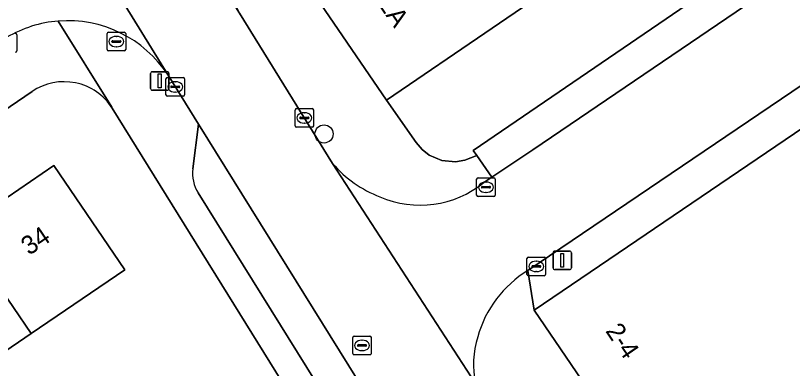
# Model space of a CAD drawing. Extents: x 160030 to 160839, y 385325 to 386450.
# Drawn here: x 160237.55 to 160279.41, y 386008.65 to 386027.68 of the extents above; entities that cross this region are included whole.
import ezdxf

# ---------------------------------------------------------------- set-up
doc = ezdxf.new("R2010")
doc.units = 0
for name, color, linetype in [('IMGEO_Boom', 7, 'Continuous'), ('IMGEO_Brandkraan', 7, 'Continuous'), ('IMGEO_Erf', 7, 'Continuous'), ('IMGEO_Kolk', 7, 'Continuous'), ('IMGEO_Lichtmast', 7, 'Continuous'), ('IMGEO_Pand', 7, 'Continuous'), ('IMGEO_Pand_nummerreeks', 7, 'Continuous'), ('IMGEO_Parkeervlak_open', 7, 'Continuous'), ('IMGEO_Rijbaan_lokaal_open', 7, 'Continuous'), ('IMGEO_Rioolput', 7, 'Continuous'), ('IMGEO_Voetpad_open', 7, 'Continuous')]:
    doc.layers.add(name, color=color, linetype=linetype)

msp = doc.modelspace()

# ---------------------------------------------------------------- linework, layer by layer
at = {"layer": 'IMGEO_Boom'}
msp.add_circle((160254.174, 386021.293), 0.489, dxfattribs=at)
at = {"layer": 'IMGEO_Brandkraan'}
for p, q in [((160242.484, 386025.846), (160242.484, 386026.698)), ((160242.559, 386026.772), (160243.411, 386026.772)), ((160242.972, 386026.552), (160242.997, 386026.552)), ((160243.485, 386026.698), (160243.485, 386025.846)), ((160242.743, 386026.266), (160242.743, 386026.278)), ((160243.181, 386026.229), (160242.783, 386026.229)), ((160242.786, 386026.315), (160243.184, 386026.315)), ((160243.227, 386026.278), (160243.227, 386026.266)), ((160243.411, 386025.772), (160242.559, 386025.772)), ((160242.995, 386025.992), (160242.97, 386025.992))]:
    msp.add_line(p, q, dxfattribs=at)
for points in [[(160242.484, 386025.846), (160242.484, 386026.698)], [(160242.559, 386026.772), (160243.411, 386026.772)], [(160243.485, 386026.698), (160243.485, 386025.846)], [(160243.411, 386025.772), (160242.559, 386025.772)]]:
    msp.add_lwpolyline(points, dxfattribs=at)
for centre, radius, start, end in [((160242.561, 386026.696), 0.0765, 91.552, 178.448), ((160242.561, 386026.696), 0.0765, 91.552, 178.448), ((160243.409, 386026.696), 0.0765, 1.552, 88.448), ((160243.409, 386026.696), 0.0765, 1.552, 88.448), ((160242.783, 386026.275), 0.0403, 85.8775, 175.7526), ((160242.78, 386026.265), 0.0366, 178.938, 274.7102), ((160243.184, 386026.272), 0.043, 264.8664, 352.4533), ((160243.188, 386026.277), 0.0386, 1.7309, 96.639), ((160242.561, 386025.848), 0.0765, 181.552, 268.448), ((160242.561, 386025.848), 0.0765, 181.552, 268.448), ((160243.409, 386025.848), 0.0765, 271.552, 358.448), ((160243.409, 386025.848), 0.0765, 271.552, 358.448)]:
    msp.add_arc(centre, radius, start, end, dxfattribs=at)
for centre, major_axis, ratio, start_param, end_param in [((160242.971, 386026.272), (-0.387, 0.002), 0.722429, 4.712389, 7.853982), ((160242.996, 386026.272), (-0.39, 0.002), 0.717154, 1.570796, 4.712389)]:
    msp.add_ellipse(centre, major_axis=major_axis, ratio=ratio, start_param=start_param, end_param=end_param, dxfattribs=at)
at = {"layer": 'IMGEO_Erf'}
for points in [[(160238.441, 386023.576), (160203.867, 386000)], [(160238.946, 385999.054), (160242.894, 386001.783), (160244.457, 385999.522), (160246.125, 386000.76), (160244.845, 386002.826), (160248.858, 386005.313), (160250.138, 386003.246), (160253.52, 386005.344), (160242.761, 386022.685)], [(160219.688, 386006.009), (160224.645, 386009.389), (160229.603, 386012.769), (160234.561, 386016.148), (160239.606, 386019.588), (160243.436, 386013.97), (160238.391, 386010.53), (160233.433, 386007.151)]]:
    msp.add_lwpolyline(points, dxfattribs=at)
msp.add_arc((160240.169, 386021.037), 3.071, 32.4491, 124.2432, dxfattribs=at)
at = {"layer": 'IMGEO_Kolk'}
for p, q in [((160237.625, 386026.628), (160237.625, 386025.776)), ((160245.654, 386023.404), (160245.654, 386024.256)), ((160245.729, 386024.33), (160246.581, 386024.33)), ((160246.142, 386024.11), (160246.167, 386024.11)), ((160246.655, 386024.256), (160246.655, 386023.404)), ((160245.913, 386023.824), (160245.913, 386023.836)), ((160246.351, 386023.787), (160245.953, 386023.787)), ((160245.956, 386023.873), (160246.354, 386023.873)), ((160246.397, 386023.836), (160246.397, 386023.824)), ((160246.581, 386023.33), (160245.729, 386023.33)), ((160246.165, 386023.55), (160246.14, 386023.55)), ((160252.612, 386021.73), (160252.612, 386022.582)), ((160252.687, 386022.656), (160253.539, 386022.656)), ((160253.1, 386022.436), (160253.125, 386022.436)), ((160253.613, 386022.582), (160253.613, 386021.73)), ((160252.871, 386022.15), (160252.871, 386022.162)), ((160253.309, 386022.113), (160252.911, 386022.113)), ((160252.914, 386022.199), (160253.312, 386022.199)), ((160253.355, 386022.162), (160253.355, 386022.15)), ((160253.539, 386021.656), (160252.687, 386021.656)), ((160253.123, 386021.876), (160253.098, 386021.876)), ((160262.393, 386017.996), (160262.393, 386018.848)), ((160262.468, 386018.922), (160263.32, 386018.922)), ((160262.881, 386018.702), (160262.906, 386018.702)), ((160263.394, 386018.848), (160263.394, 386017.996)), ((160262.652, 386018.416), (160262.652, 386018.428)), ((160263.09, 386018.379), (160262.692, 386018.379)), ((160262.695, 386018.465), (160263.093, 386018.465)), ((160263.136, 386018.428), (160263.136, 386018.416)), ((160263.32, 386017.922), (160262.468, 386017.922)), ((160262.904, 386018.142), (160262.879, 386018.142)), ((160265.106, 386013.724), (160265.106, 386014.576)), ((160265.181, 386014.65), (160266.033, 386014.65)), ((160265.594, 386014.43), (160265.619, 386014.43)), ((160266.107, 386014.576), (160266.107, 386013.724)), ((160265.365, 386014.144), (160265.365, 386014.156)), ((160265.803, 386014.107), (160265.405, 386014.107)), ((160265.408, 386014.193), (160265.806, 386014.193)), ((160265.849, 386014.156), (160265.849, 386014.144)), ((160266.033, 386013.65), (160265.181, 386013.65)), ((160265.617, 386013.87), (160265.592, 386013.87))]:
    msp.add_line(p, q, dxfattribs=at)
for points in [[(160237.625, 386026.628), (160237.625, 386025.776)], [(160245.654, 386023.404), (160245.654, 386024.256)], [(160245.729, 386024.33), (160246.581, 386024.33)], [(160246.655, 386024.256), (160246.655, 386023.404)], [(160246.581, 386023.33), (160245.729, 386023.33)], [(160252.612, 386021.73), (160252.612, 386022.582)], [(160252.687, 386022.656), (160253.539, 386022.656)], [(160253.613, 386022.582), (160253.613, 386021.73)], [(160253.539, 386021.656), (160252.687, 386021.656)], [(160262.393, 386017.996), (160262.393, 386018.848)], [(160262.468, 386018.922), (160263.32, 386018.922)], [(160263.394, 386018.848), (160263.394, 386017.996)], [(160263.32, 386017.922), (160262.468, 386017.922)], [(160265.106, 386013.724), (160265.106, 386014.576)], [(160265.181, 386014.65), (160266.033, 386014.65)], [(160266.107, 386014.576), (160266.107, 386013.724)], [(160266.033, 386013.65), (160265.181, 386013.65)]]:
    msp.add_lwpolyline(points, dxfattribs=at)
for centre, radius, start, end in [((160237.549, 386026.626), 0.0765, 1.552, 88.448), ((160237.549, 386026.626), 0.0765, 1.552, 88.448), ((160237.549, 386025.778), 0.0765, 271.552, 358.448), ((160237.549, 386025.778), 0.0765, 271.552, 358.448), ((160245.731, 386024.254), 0.0765, 91.552, 178.448), ((160245.731, 386024.254), 0.0765, 91.552, 178.448), ((160246.579, 386024.254), 0.0765, 1.552, 88.448), ((160246.579, 386024.254), 0.0765, 1.552, 88.448), ((160245.953, 386023.833), 0.0403, 85.8775, 175.7526), ((160245.95, 386023.823), 0.0366, 178.938, 274.7102), ((160246.354, 386023.83), 0.043, 264.8664, 352.4533), ((160246.358, 386023.835), 0.0386, 1.7309, 96.639), ((160245.731, 386023.406), 0.0765, 181.552, 268.448), ((160245.731, 386023.406), 0.0765, 181.552, 268.448), ((160246.579, 386023.406), 0.0765, 271.552, 358.448), ((160246.579, 386023.406), 0.0765, 271.552, 358.448), ((160252.689, 386022.58), 0.0765, 91.552, 178.448), ((160252.689, 386022.58), 0.0765, 91.552, 178.448), ((160253.537, 386022.58), 0.0765, 1.552, 88.448), ((160253.537, 386022.58), 0.0765, 1.552, 88.448), ((160252.911, 386022.159), 0.0403, 85.8775, 175.7526), ((160252.908, 386022.149), 0.0366, 178.938, 274.7102), ((160253.312, 386022.156), 0.043, 264.8664, 352.4533), ((160253.316, 386022.161), 0.0386, 1.7309, 96.639), ((160252.689, 386021.732), 0.0765, 181.552, 268.448), ((160252.689, 386021.732), 0.0765, 181.552, 268.448), ((160253.537, 386021.732), 0.0765, 271.552, 358.448), ((160253.537, 386021.732), 0.0765, 271.552, 358.448), ((160262.47, 386018.846), 0.0765, 91.552, 178.448), ((160262.47, 386018.846), 0.0765, 91.552, 178.448), ((160263.318, 386018.846), 0.0765, 1.552, 88.448), ((160263.318, 386018.846), 0.0765, 1.552, 88.448), ((160262.692, 386018.425), 0.0403, 85.8775, 175.7526), ((160262.689, 386018.415), 0.0366, 178.938, 274.7102), ((160263.093, 386018.422), 0.043, 264.8664, 352.4533), ((160263.097, 386018.427), 0.0386, 1.7309, 96.639), ((160262.47, 386017.998), 0.0765, 181.552, 268.448), ((160262.47, 386017.998), 0.0765, 181.552, 268.448), ((160263.318, 386017.998), 0.0765, 271.552, 358.448), ((160263.318, 386017.998), 0.0765, 271.552, 358.448), ((160265.183, 386014.574), 0.0765, 91.552, 178.448), ((160265.183, 386014.574), 0.0765, 91.552, 178.448), ((160266.031, 386014.574), 0.0765, 1.552, 88.448), ((160266.031, 386014.574), 0.0765, 1.552, 88.448), ((160265.405, 386014.153), 0.0403, 85.8775, 175.7526), ((160265.402, 386014.143), 0.0366, 178.938, 274.7102), ((160265.806, 386014.15), 0.043, 264.8664, 352.4533), ((160265.81, 386014.155), 0.0386, 1.7309, 96.639), ((160265.183, 386013.726), 0.0765, 181.552, 268.448), ((160265.183, 386013.726), 0.0765, 181.552, 268.448), ((160266.031, 386013.726), 0.0765, 271.552, 358.448), ((160266.031, 386013.726), 0.0765, 271.552, 358.448)]:
    msp.add_arc(centre, radius, start, end, dxfattribs=at)
for centre, major_axis, ratio, start_param, end_param in [((160246.141, 386023.83), (-0.387, 0.002), 0.722429, 4.712389, 7.853982), ((160246.166, 386023.83), (-0.39, 0.002), 0.717154, 1.570796, 4.712389), ((160253.099, 386022.156), (-0.387, 0.002), 0.722429, 4.712389, 7.853982), ((160253.124, 386022.156), (-0.39, 0.002), 0.717154, 1.570796, 4.712389), ((160262.88, 386018.422), (-0.387, 0.002), 0.722429, 4.712389, 7.853982), ((160262.905, 386018.422), (-0.39, 0.002), 0.717154, 1.570796, 4.712389), ((160265.593, 386014.15), (-0.387, 0.002), 0.722429, 4.712389, 7.853982), ((160265.618, 386014.15), (-0.39, 0.002), 0.717154, 1.570796, 4.712389)]:
    msp.add_ellipse(centre, major_axis=major_axis, ratio=ratio, start_param=start_param, end_param=end_param, dxfattribs=at)
at = {"layer": 'IMGEO_Lichtmast'}
for p, q in [((160244.824, 386023.749), (160244.824, 386024.549)), ((160244.824, 386024.549), (160244.824, 386023.749)), ((160244.924, 386024.649), (160245.714, 386024.649)), ((160245.714, 386024.649), (160244.924, 386024.649)), ((160245.814, 386024.549), (160245.814, 386023.749)), ((160245.814, 386023.749), (160245.814, 386024.549)), ((160245.714, 386023.649), (160244.924, 386023.649)), ((160244.924, 386023.649), (160245.714, 386023.649)), ((160266.512, 386014.08), (160266.512, 386014.88)), ((160266.512, 386014.88), (160266.512, 386014.08)), ((160266.612, 386014.98), (160267.402, 386014.98)), ((160267.402, 386014.98), (160266.612, 386014.98)), ((160267.502, 386014.88), (160267.502, 386014.08)), ((160267.502, 386014.08), (160267.502, 386014.88)), ((160267.402, 386013.98), (160266.612, 386013.98)), ((160266.612, 386013.98), (160267.402, 386013.98))]:
    msp.add_line(p, q, dxfattribs=at)
for points in [[(160245.244, 386024.524), (160245.394, 386024.524), (160245.394, 386023.774), (160245.244, 386023.774), (160245.244, 386024.524)], [(160266.932, 386014.855), (160267.082, 386014.855), (160267.082, 386014.105), (160266.932, 386014.105), (160266.932, 386014.855)]]:
    msp.add_lwpolyline(points, dxfattribs=at)
for centre, start, end in [((160244.924, 386024.549), 90, 180), ((160244.924, 386024.549), 90, 180), ((160245.714, 386024.549), 0, 90), ((160245.714, 386024.549), 360, 90), ((160244.924, 386023.749), 180, 270), ((160244.924, 386023.749), 180, 270), ((160245.714, 386023.749), 270, 0), ((160245.714, 386023.749), 270, 0), ((160266.612, 386014.88), 90, 180), ((160266.612, 386014.88), 90, 180), ((160267.402, 386014.88), 0, 90), ((160267.402, 386014.88), 360, 90), ((160266.612, 386014.08), 180, 270), ((160266.612, 386014.08), 180, 270), ((160267.402, 386014.08), 270, 0), ((160267.402, 386014.08), 270, 0)]:
    msp.add_arc(centre, 0.1, start, end, dxfattribs=at)
at = {"layer": 'IMGEO_Pand'}
msp.add_lwpolyline([(160329.094, 386054.994), (160265.499, 386011.79), (160270.054, 386005.085)], dxfattribs=at)
for points in [[(160286.007, 386042.54), (160285.171, 386043.767), (160281.819, 386048.768), (160281.71, 386048.693), (160279.189, 386046.974), (160265.251, 386037.468), (160262.185, 386035.376), (160253.307, 386029.321), (160257.536, 386023.121)], [(160238.391, 386010.53), (160243.436, 386013.97), (160239.606, 386019.588), (160234.561, 386016.148)], [(160233.433, 386007.151), (160238.391, 386010.53), (160234.561, 386016.148), (160229.603, 386012.769)]]:
    msp.add_lwpolyline(points, close=True, dxfattribs=at)
at = {"layer": 'IMGEO_Parkeervlak_open'}
for points in [[(160247.407, 386021.819), (160247.102, 386019.418)], [(160265.703, 385991.996), (160260.98, 386000), (160258.344, 386004.227), (160247.407, 386021.819)], [(160247.388, 386018.111), (160256.668, 386003.183), (160258.653, 386000), (160260.614, 385996.846), (160261.948, 385994.543)]]:
    msp.add_lwpolyline(points, dxfattribs=at)
msp.add_arc((160249.096, 386019.169), 2.009, 172.893, 211.793, dxfattribs=at)
at = {"layer": 'IMGEO_Rijbaan_lokaal_open'}
for points in [[(160189.926, 386114.094), (160191.24, 386111.976), (160198.933, 386099.578), (160234.281, 386042.907), (160236.171, 386039.885), (160236.489, 386039.496), (160245.768, 386024.457), (160247.407, 386021.819), (160258.344, 386004.227), (160260.98, 386000), (160265.703, 385991.996)], [(160262.33, 386007.837), (160254.635, 386019.699), (160249.611, 386027.802), (160240.779, 386041.933), (160240.647, 386042.176), (160219.316, 386076.396)], [(160325.342, 386061.172), (160323.666, 386060.015), (160315.833, 386054.695), (160308.389, 386049.542), (160302.814, 386045.834), (160265.416, 386020.437), (160263.212, 386018.961), (160262.779, 386018.671)], [(160265.152, 386013.927), (160289.489, 386030.427), (160310.109, 386044.387), (160328.103, 386056.609)], [(160245.768, 386024.457), (160236.489, 386039.496), (160236.171, 386039.885)], [(160254.635, 386019.699), (160262.33, 386007.837)]]:
    msp.add_lwpolyline(points, dxfattribs=at)
msp.add_lwpolyline([(160259.141, 386020.837), (160259.455, 386020.461), (160259.843, 386020.155), (160260.524, 386019.862), (160261.262, 386019.794), (160261.75, 386019.877), (160262.397, 386020.134), (160262.208, 386020.406), (160288.716, 386038.505), (160286.007, 386042.54), (160257.536, 386023.121)], close=True, dxfattribs=at)
for centre, radius, start, end in [((160240.368, 386020.961), 6.437, 94.617, 120.6267), ((160240.365, 386020.963), 6.434, 32.8863, 94.5894), ((160259.436, 386023.801), 6.315, 220.5147, 249.0519), ((160259.347, 386022.898), 5.445, 246.522, 309.0732), ((160268.308, 386008.735), 6.076, 121.2973, 164.5484), ((160267.23, 386008.861), 5.006, 162.6458, 191.8042)]:
    msp.add_arc(centre, radius, start, end, dxfattribs=at)
at = {"layer": 'IMGEO_Rioolput'}
for p, q in [((160255.719, 386009.466), (160255.719, 386010.318)), ((160255.794, 386010.392), (160256.646, 386010.392)), ((160256.72, 386010.318), (160256.72, 386009.466)), ((160255.978, 386009.886), (160255.978, 386009.898)), ((160256.416, 386009.849), (160256.018, 386009.849)), ((160256.021, 386009.935), (160256.419, 386009.935)), ((160256.207, 386010.172), (160256.232, 386010.172)), ((160256.462, 386009.898), (160256.462, 386009.886)), ((160256.646, 386009.392), (160255.794, 386009.392)), ((160256.23, 386009.612), (160256.205, 386009.612))]:
    msp.add_line(p, q, dxfattribs=at)
for points in [[(160255.719, 386009.466), (160255.719, 386010.318)], [(160255.794, 386010.392), (160256.646, 386010.392)], [(160256.72, 386010.318), (160256.72, 386009.466)], [(160256.646, 386009.392), (160255.794, 386009.392)]]:
    msp.add_lwpolyline(points, dxfattribs=at)
for centre, radius, start, end in [((160255.796, 386010.316), 0.0765, 91.552, 178.448), ((160255.796, 386010.316), 0.0765, 91.552, 178.448), ((160256.644, 386010.316), 0.0765, 1.552, 88.448), ((160256.644, 386010.316), 0.0765, 1.552, 88.448), ((160256.018, 386009.895), 0.0403, 85.8775, 175.7526), ((160256.015, 386009.885), 0.0366, 178.938, 274.7102), ((160256.419, 386009.892), 0.043, 264.8664, 352.4533), ((160256.423, 386009.897), 0.0386, 1.7309, 96.639), ((160255.796, 386009.468), 0.0765, 181.552, 268.448), ((160255.796, 386009.468), 0.0765, 181.552, 268.448), ((160256.644, 386009.468), 0.0765, 271.552, 358.448), ((160256.644, 386009.468), 0.0765, 271.552, 358.448)]:
    msp.add_arc(centre, radius, start, end, dxfattribs=at)
for centre, major_axis, ratio, start_param, end_param in [((160256.206, 386009.892), (-0.387, 0.002), 0.722429, 4.712389, 7.853982), ((160256.231, 386009.892), (-0.39, 0.002), 0.717154, 1.570796, 4.712389)]:
    msp.add_ellipse(centre, major_axis=major_axis, ratio=ratio, start_param=start_param, end_param=end_param, dxfattribs=at)
at = {"layer": 'IMGEO_Voetpad_open'}
for points in [[(160328.103, 386056.609), (160310.109, 386044.387), (160289.489, 386030.427), (160265.152, 386013.927), (160265.499, 386011.79), (160329.094, 386054.994)], [(160262.779, 386018.671), (160263.212, 386018.961), (160262.397, 386020.134), (160261.75, 386019.877), (160261.262, 386019.794), (160260.524, 386019.862), (160259.843, 386020.155), (160259.455, 386020.461), (160259.141, 386020.837), (160257.536, 386023.121), (160253.307, 386029.321)], [(160249.402, 386028.229), (160249.611, 386027.802), (160254.635, 386019.699)], [(160167.418, 386027.548), (160186.061, 386000), (160191.684, 385991.692), (160192.591, 385992.311), (160203.867, 386000), (160238.441, 386023.576)], [(160239.85, 386027.377), (160242.738, 386022.732), (160242.761, 386022.685), (160253.52, 386005.344), (160254.37, 386003.975), (160256.836, 386000), (160260.377, 385994.292), (160262.346, 385991.267), (160262.461, 385991.324), (160265.082, 385987.119), (160267.741, 385988.807), (160266.076, 385991.5)], [(160242.761, 386022.685), (160242.738, 386022.732), (160239.85, 386027.377)], [(160247.102, 386019.418), (160247.407, 386021.819), (160245.768, 386024.457)], [(160261.948, 385994.543), (160260.614, 385996.846), (160258.653, 386000), (160256.668, 386003.183), (160247.388, 386018.111)], [(160267.348, 386003.247), (160270.054, 386005.085), (160265.499, 386011.79), (160265.152, 386013.927)]]:
    msp.add_lwpolyline(points, dxfattribs=at)
msp.add_lwpolyline([(160308.389, 386049.542), (160307.267, 386051.171), (160294.438, 386042.412), (160292.172, 386040.865), (160288.716, 386038.505), (160262.208, 386020.406), (160262.397, 386020.134), (160263.212, 386018.961), (160265.416, 386020.437), (160302.814, 386045.834)], close=True, dxfattribs=at)
for centre, radius, start, end in [((160240.368, 386020.961), 6.437, 94.617, 120.6267), ((160240.365, 386020.963), 6.434, 32.8863, 94.5894), ((160240.169, 386021.037), 3.071, 32.4491, 124.2432), ((160259.436, 386023.801), 6.315, 220.5147, 249.0519), ((160249.096, 386019.169), 2.009, 172.893, 211.793), ((160259.347, 386022.898), 5.445, 246.522, 309.0732), ((160268.308, 386008.735), 6.076, 121.2973, 164.5484), ((160267.23, 386008.861), 5.006, 162.6458, 191.8042)]:
    msp.add_arc(centre, radius, start, end, dxfattribs=at)

# ---------------------------------------------------------------- texts
at = {"layer": 'IMGEO_Pand_nummerreeks'}
for s, rotation, p in [('2A', 304.297, (160257.05, 386028.306)), ('34', 34.2834, (160238.283, 386014.717)), ('2-4', 304.1939, (160269.305, 386010.671))]:
    msp.add_text(s, height=1, rotation=rotation, dxfattribs=at).set_placement(p)

doc.saveas('drawing.dxf')
